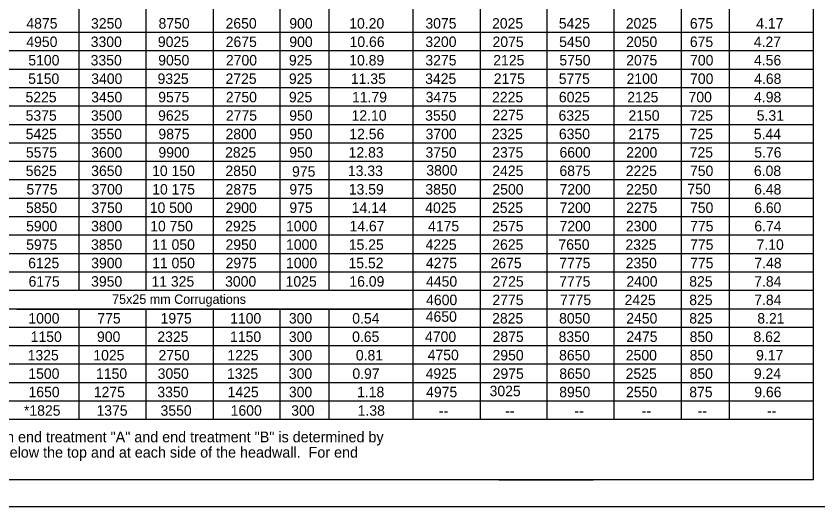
# Model space of a CAD drawing. Extents: x 1083.1 to 1117.1, y 675.4 to 741.4.
# Drawn here: x 1091.76 to 1103.72, y 697.85 to 705.19 of the extents above; entities that cross this region are included whole.
import ezdxf

# ---------------------------------------------------------------- set-up
doc = ezdxf.new("R2010")
doc.units = 0
doc.layers.add('Level 1', color=7, linetype='Continuous')

msp = doc.modelspace()

# ---------------------------------------------------------------- linework, layer by layer
at = {"layer": 'Level 1'}
for p, q in [((1103.658, 698.26), (1103.658, 713.109)), ((1097.684, 699.159), (1097.684, 712.709)), ((1101.686, 699.159), (1101.686, 708.79)), ((1102.402, 699.159), (1102.402, 708.79)), ((1098.687, 699.159), (1098.687, 708.512)), ((1092.703, 701.086), (1092.703, 707.693)), ((1093.699, 701.085), (1093.699, 707.692)), ((1094.708, 701.085), (1094.708, 707.691)), ((1095.702, 701.086), (1095.702, 707.69)), ((1096.433, 701.087), (1096.433, 707.689)), ((1098.687, 700.427), (1098.687, 707.623)), ((1099.686, 700.427), (1099.686, 707.623)), ((1099.686, 699.159), (1099.686, 707.623)), ((1100.686, 700.427), (1100.686, 707.623)), ((1100.686, 699.159), (1100.686, 707.623)), ((1103.658, 704.941), (1086.478, 704.941)), ((1103.658, 704.665), (1086.478, 704.665)), ((1103.658, 704.39), (1086.478, 704.39)), ((1103.658, 704.115), (1086.478, 704.115)), ((1103.658, 703.839), (1086.478, 703.839)), ((1103.658, 703.564), (1086.478, 703.564)), ((1103.658, 703.289), (1086.478, 703.289)), ((1100.181, 703.295), (1100.181, 703.295)), ((1102.047, 703.295), (1102.047, 703.295)), ((1103.658, 703.014), (1086.478, 703.014)), ((1103.658, 702.738), (1086.478, 702.738)), ((1103.658, 702.463), (1086.478, 702.463)), ((1103.658, 702.188), (1086.478, 702.188)), ((1103.658, 701.912), (1086.478, 701.912)), ((1103.658, 701.637), (1086.478, 701.637)), ((1103.658, 701.361), (1086.478, 701.361)), ((1103.658, 701.086), (1086.478, 701.086)), ((1097.699, 701.086), (1091.762, 701.086)), ((1103.658, 700.811), (1086.478, 700.811)), ((1091.77, 700.811), (1097.694, 700.811)), ((1092.703, 699.159), (1092.703, 700.809)), ((1093.699, 699.159), (1093.699, 700.811)), ((1094.708, 699.159), (1094.708, 700.811)), ((1095.702, 699.159), (1095.702, 700.811)), ((1096.433, 699.159), (1096.433, 700.811)), ((1103.658, 700.535), (1086.478, 700.535)), ((1103.658, 700.26), (1086.478, 700.26)), ((1103.658, 699.985), (1086.478, 699.985)), ((1103.658, 699.709), (1086.478, 699.709)), ((1103.658, 699.434), (1086.478, 699.434)), ((1093.452, 699.323), (1093.452, 699.323)), ((1094.453, 699.323), (1094.453, 699.323)), ((1095.318, 699.323), (1095.318, 699.323)), ((1096.319, 699.323), (1096.319, 699.323)), ((1103.658, 699.159), (1086.48, 699.159)), ((1103.658, 698.26), (1086.478, 698.26)), ((1098.966, 698.262), (1100.368, 698.262))]:
    msp.add_line(p, q, dxfattribs=at)
msp.add_lwpolyline([(1085.126, 718.854), (1116.626, 718.854), (1116.626, 697.854), (1085.126, 697.854)], close=True, dxfattribs=at)

# ---------------------------------------------------------------- texts
for s, height, p in [('4875', 0.156, (1091.914, 704.999)), ('3250', 0.156, (1092.878, 704.999)), ('8750', 0.156, (1093.886, 704.999)), ('2650', 0.156, (1094.886, 704.999)), ('900', 0.156, (1095.837, 704.999)), ('10.20', 0.156, (1096.731, 704.999)), ('3075', 0.156, (1097.867, 704.999)), ('2025', 0.156, (1098.862, 704.999)), ('5425', 0.156, (1099.858, 704.999)), ('2025', 0.156, (1100.857, 704.999)), ('675', 0.156, (1101.813, 704.999)), ('4.17', 0.156, (1102.802, 704.999)), ('4950', 0.156, (1091.913, 704.724)), ('3300', 0.156, (1092.874, 704.724)), ('9025', 0.156, (1093.876, 704.724)), ('2675', 0.156, (1094.888, 704.724)), ('900', 0.156, (1095.837, 704.724)), ('10.66', 0.156, (1096.736, 704.724)), ('3200', 0.156, (1097.867, 704.724)), ('2075', 0.156, (1098.869, 704.724)), ('5450', 0.156, (1099.863, 704.724)), ('2050', 0.156, (1100.862, 704.724)), ('675', 0.156, (1101.813, 704.724)), ('4.27', 0.156, (1102.767, 704.724)), ('5100', 0.156, (1091.943, 704.449)), ('3350', 0.156, (1092.873, 704.449)), ('9050', 0.156, (1093.881, 704.449)), ('2700', 0.156, (1094.891, 704.449)), ('925', 0.156, (1095.831, 704.449)), ('10.89', 0.156, (1096.731, 704.449)), ('3275', 0.156, (1097.867, 704.449)), ('2125', 0.156, (1098.88, 704.449)), ('5750', 0.156, (1099.866, 704.449)), ('2075', 0.156, (1100.863, 704.449)), ('700', 0.156, (1101.816, 704.449)), ('4.56', 0.156, (1102.77, 704.449)), ('5150', 0.156, (1091.941, 704.173)), ('3400', 0.156, (1092.882, 704.173)), ('9325', 0.156, (1093.871, 704.173)), ('2725', 0.156, (1094.885, 704.173)), ('925', 0.156, (1095.831, 704.173)), ('11.35', 0.156, (1096.755, 704.173)), ('3425', 0.156, (1097.864, 704.173)), ('2175', 0.156, (1098.887, 704.173)), ('5775', 0.156, (1099.857, 704.173)), ('2100', 0.156, (1100.869, 704.173)), ('700', 0.156, (1101.816, 704.173)), ('4.68', 0.156, (1102.772, 704.173)), ('5225', 0.156, (1091.901, 703.898)), ('3450', 0.156, (1092.881, 703.898)), ('9575', 0.156, (1093.881, 703.898)), ('2750', 0.156, (1094.89, 703.898)), ('925', 0.156, (1095.831, 703.898)), ('11.79', 0.156, (1096.772, 703.898)), ('3475', 0.156, (1097.871, 703.898)), ('2225', 0.156, (1098.862, 703.898)), ('6025', 0.156, (1099.859, 703.898)), ('2125', 0.156, (1100.879, 703.898)), ('700', 0.156, (1101.793, 703.898)), ('4.98', 0.156, (1102.771, 703.898)), ('5375', 0.156, (1091.903, 703.623)), ('3500', 0.156, (1092.878, 703.623)), ('9625', 0.156, (1093.879, 703.623)), ('2775', 0.156, (1094.891, 703.623)), ('950', 0.156, (1095.836, 703.623)), ('12.10', 0.156, (1096.766, 703.623)), ('3550', 0.156, (1097.864, 703.623)), ('2275', 0.156, (1098.868, 703.631)), ('6325', 0.156, (1099.854, 703.623)), ('2150', 0.156, (1100.897, 703.623)), ('725', 0.156, (1101.81, 703.623)), ('5.31', 0.156, (1102.811, 703.623)), ('5425', 0.156, (1091.904, 703.347)), ('3550', 0.156, (1092.877, 703.347)), ('9875', 0.156, (1093.884, 703.347)), ('2800', 0.156, (1094.885, 703.347)), ('950', 0.156, (1095.836, 703.347)), ('12.56', 0.156, (1096.732, 703.347)), ('3700', 0.156, (1097.87, 703.347)), ('2325', 0.156, (1098.857, 703.347)), ('6350', 0.156, (1099.859, 703.347)), ('2175', 0.156, (1100.898, 703.347)), ('725', 0.156, (1101.81, 703.347)), ('5.44', 0.156, (1102.767, 703.347)), ('5575', 0.156, (1091.907, 703.072)), ('3600', 0.156, (1092.882, 703.072)), ('9900', 0.156, (1093.884, 703.072)), ('2825', 0.156, (1094.879, 703.072)), ('950', 0.156, (1095.836, 703.072)), ('12.83', 0.156, (1096.722, 703.072)), ('3750', 0.156, (1097.869, 703.072)), ('2375', 0.156, (1098.864, 703.072)), ('6600', 0.156, (1099.868, 703.072)), ('2200', 0.156, (1100.863, 703.072)), ('725', 0.156, (1101.81, 703.072)), ('5.76', 0.156, (1102.774, 703.072)), ('5625', 0.156, (1091.904, 702.797)), ('3650', 0.156, (1092.881, 702.797)), ('10 150', 0.156, (1093.79, 702.797)), ('2850', 0.156, (1094.884, 702.797)), ('975', 0.156, (1095.878, 702.787)), ('13.33', 0.156, (1096.711, 702.797)), ('3800', 0.156, (1097.881, 702.805)), ('2425', 0.156, (1098.865, 702.797)), ('6875', 0.156, (1099.867, 702.797)), ('2225', 0.156, (1100.857, 702.797)), ('750', 0.156, (1101.815, 702.797)), ('6.08', 0.156, (1102.769, 702.797)), ('5775', 0.156, (1091.915, 702.521)), ('3700', 0.156, (1092.886, 702.521)), ('10 175', 0.156, (1093.791, 702.521)), ('2875', 0.156, (1094.886, 702.521)), ('975', 0.156, (1095.838, 702.521)), ('13.59', 0.156, (1096.724, 702.521)), ('3850', 0.156, (1097.867, 702.521)), ('2500', 0.156, (1098.867, 702.521)), ('7200', 0.156, (1099.869, 702.521)), ('2250', 0.156, (1100.862, 702.521)), ('750', 0.156, (1101.776, 702.525)), ('6.48', 0.156, (1102.772, 702.521)), ('5850', 0.156, (1091.908, 702.246)), ('3750', 0.156, (1092.885, 702.246)), ('10 500', 0.156, (1093.755, 702.246)), ('2900', 0.156, (1094.887, 702.246)), ('975', 0.156, (1095.838, 702.246)), ('14.14', 0.156, (1096.768, 702.246)), ('4025', 0.156, (1097.865, 702.246)), ('2525', 0.156, (1098.861, 702.246)), ('7200', 0.156, (1099.869, 702.246)), ('2275', 0.156, (1100.863, 702.246)), ('750', 0.156, (1101.815, 702.246)), ('6.60', 0.156, (1102.772, 702.246)), ('5900', 0.156, (1091.91, 701.971)), ('3800', 0.156, (1092.88, 701.971)), ('10 750', 0.156, (1093.761, 701.971)), ('2925', 0.156, (1094.88, 701.971)), ('1000', 0.156, (1095.788, 701.971)), ('14.67', 0.156, (1096.735, 701.971)), ('4175', 0.156, (1097.907, 701.971)), ('2575', 0.156, (1098.867, 701.971)), ('7200', 0.156, (1099.869, 701.971)), ('2300', 0.156, (1100.858, 701.971)), ('775', 0.156, (1101.817, 701.971)), ('6.74', 0.156, (1102.775, 701.971)), ('5975', 0.156, (1091.911, 701.695)), ('3850', 0.156, (1092.879, 701.695)), ('11 050', 0.156, (1093.79, 701.695)), ('2950', 0.156, (1094.885, 701.695)), ('1000', 0.156, (1095.788, 701.695)), ('15.25', 0.156, (1096.724, 701.695)), ('4225', 0.156, (1097.869, 701.695)), ('2625', 0.156, (1098.865, 701.695)), ('7650', 0.156, (1099.852, 701.695)), ('2325', 0.156, (1100.852, 701.695)), ('775', 0.156, (1101.817, 701.695)), ('7.10', 0.156, (1102.808, 701.695)), ('6125', 0.156, (1091.941, 701.42)), ('3900', 0.156, (1092.881, 701.42)), ('11 050', 0.156, (1093.79, 701.42)), ('2975', 0.156, (1094.887, 701.42)), ('1000', 0.156, (1095.788, 701.42)), ('15.52', 0.156, (1096.72, 701.42)), ('4275', 0.156, (1097.875, 701.42)), ('2675', 0.156, (1098.839, 701.42)), ('7775', 0.156, (1099.865, 701.42)), ('2350', 0.156, (1100.856, 701.42)), ('775', 0.156, (1101.817, 701.42)), ('7.48', 0.156, (1102.776, 701.42)), ('6175', 0.156, (1091.947, 701.145)), ('3950', 0.156, (1092.88, 701.145)), ('11 325', 0.156, (1093.78, 701.145)), ('3000', 0.156, (1094.879, 701.145)), ('1025', 0.156, (1095.782, 701.145)), ('16.09', 0.156, (1096.733, 701.145)), ('4450', 0.156, (1097.877, 701.145)), ('2725', 0.156, (1098.869, 701.145)), ('7775', 0.156, (1099.865, 701.145)), ('2400', 0.156, (1100.866, 701.145)), ('825', 0.156, (1101.804, 701.145)), ('7.84', 0.156, (1102.773, 701.145)), ('75x25 mm Corrugations', 0.14, (1093.193, 700.888)), ('4600', 0.156, (1097.878, 700.869)), ('2775', 0.156, (1098.867, 700.869)), ('7775', 0.156, (1099.876, 700.869)), ('2425', 0.156, (1100.839, 700.869)), ('825', 0.156, (1101.804, 700.869)), ('7.84', 0.156, (1102.773, 700.869)), ('4650', 0.156, (1097.873, 700.62)), ('1000', 0.156, (1091.944, 700.594)), ('775', 0.156, (1092.973, 700.594)), ('1975', 0.156, (1093.917, 700.594)), ('1100', 0.156, (1094.954, 700.594)), ('300', 0.156, (1095.83, 700.594)), ('0.54', 0.156, (1096.776, 700.594)), ('2825', 0.156, (1098.863, 700.594)), ('8050', 0.156, (1099.862, 700.594)), ('2450', 0.156, (1100.864, 700.594)), ('825', 0.156, (1101.804, 700.594)), ('8.21', 0.156, (1102.819, 700.594)), ('1150', 0.156, (1091.978, 700.319)), ('900', 0.156, (1092.968, 700.319)), ('2325', 0.156, (1093.868, 700.319)), ('1150', 0.156, (1094.953, 700.319)), ('300', 0.156, (1095.83, 700.319)), ('0.65', 0.156, (1096.774, 700.319)), ('4700', 0.156, (1097.862, 700.319)), ('2875', 0.156, (1098.87, 700.319)), ('8350', 0.156, (1099.854, 700.319)), ('2475', 0.156, (1100.866, 700.319)), ('850', 0.156, (1101.809, 700.319)), ('8.62', 0.156, (1102.762, 700.319)), ('1325', 0.156, (1091.933, 700.043)), ('1025', 0.156, (1092.913, 700.043)), ('2750', 0.156, (1093.885, 700.043)), ('1225', 0.156, (1094.913, 700.043)), ('300', 0.156, (1095.83, 700.043)), ('0.81', 0.156, (1096.83, 700.043)), ('4750', 0.156, (1097.901, 700.046)), ('2950', 0.156, (1098.869, 700.043)), ('8650', 0.156, (1099.862, 700.043)), ('2500', 0.156, (1100.857, 700.043)), ('850', 0.156, (1101.809, 700.043)), ('9.17', 0.156, (1102.801, 700.043)), ('1500', 0.156, (1091.943, 699.768)), ('1150', 0.156, (1092.953, 699.768)), ('3050', 0.156, (1093.873, 699.768)), ('1325', 0.156, (1094.908, 699.768)), ('300', 0.156, (1095.83, 699.768)), ('0.97', 0.156, (1096.778, 699.768)), ('4925', 0.156, (1097.871, 699.768)), ('2975', 0.156, (1098.871, 699.768)), ('8650', 0.156, (1099.865, 699.768)), ('2525', 0.156, (1100.855, 699.768)), ('850', 0.156, (1101.809, 699.768)), ('9.24', 0.156, (1102.768, 699.768)), ('1650', 0.156, (1091.946, 699.493)), ('1275', 0.156, (1092.92, 699.493)), ('3350', 0.156, (1093.868, 699.493)), ('1425', 0.156, (1094.916, 699.493)), ('300', 0.156, (1095.83, 699.493)), ('1.18', 0.156, (1096.848, 699.493)), ('4975', 0.156, (1097.878, 699.493)), ('3025', 0.156, (1098.825, 699.509)), ('8950', 0.156, (1099.864, 699.493)), ('2550', 0.156, (1100.86, 699.493)), ('875', 0.156, (1101.804, 699.493)), ('9.66', 0.156, (1102.774, 699.493)), ('*1825', 0.156, (1091.878, 699.217)), ('1375', 0.156, (1092.96, 699.217)), ('3550', 0.156, (1093.916, 699.217)), ('1600', 0.156, (1094.962, 699.217)), ('300', 0.156, (1095.866, 699.217)), ('1.38', 0.156, (1096.857, 699.217)), ('--', 0.16, (1098.067, 699.21)), ('--', 0.16, (1099.056, 699.21)), ('--', 0.16, (1100.089, 699.21)), ('--', 0.16, (1101.093, 699.21)), ('--', 0.16, (1101.928, 699.21)), ('--', 0.16, (1102.962, 699.21)), ('* Channel configuration for pipe sizes between end treatment "A" and end treatment "B" is determined by', 0.16, (1087.318, 698.82)), ('  2:1 slopes passing through a point 6" [150] below the top and at each side of the headwall.  For end', 0.16, (1087.318, 698.591))]:
    msp.add_text(s, height=height, dxfattribs=at).set_placement(p)

doc.saveas('drawing.dxf')
